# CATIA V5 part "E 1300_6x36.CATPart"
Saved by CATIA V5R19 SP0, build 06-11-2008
Definition: E 1300_6x36
Nomenclature: E 1300_6x36
Description: PART-E 1300_6x36-DESC
Material "Steel": density 7860 kg/m3, Young's modulus 2e+11 Pa, Poisson ratio 0.266, thermal expansion 1.17e-05 1/K
Bounding box of the stored display mesh (mm): x -3 to 3, y -156 to -150, z 9 to 45
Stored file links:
  G:\UTB\Kombinované\Bakalářská práce\Catia\FORMA\E 1300_6x36.CATPart
  D:\Aplikace\CATIA\Nová složka\win_b64\startup\materials\Catalog.CATMaterial
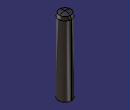
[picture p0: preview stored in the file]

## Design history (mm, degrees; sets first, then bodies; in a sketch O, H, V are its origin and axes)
Body1 "E 1300_6x36" (main body)
  Solid1: solid without history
